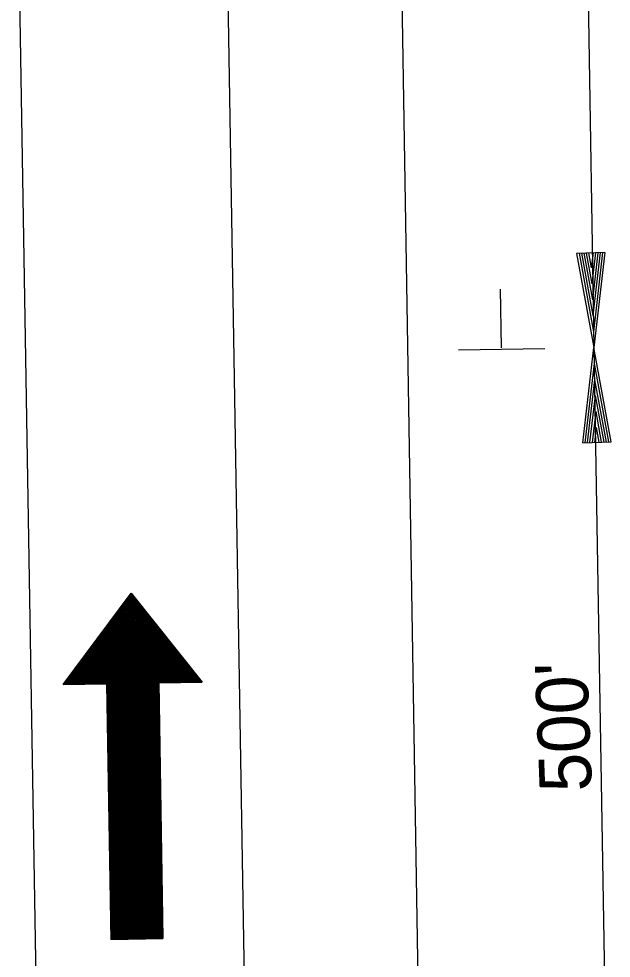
# Model space of a CAD drawing. Extents: x 1676063 to 1678026, y 228339 to 229904.
# Drawn here: x 1677124.4 to 1677192.4, y 228807.7 to 228915.5 of the extents above; entities that cross this region are included whole.
import ezdxf

# ---------------------------------------------------------------- set-up
doc = ezdxf.new("R2010")
doc.units = 0
for name, color, linetype in [('R_Annotation', 7, 'Continuous'), ('R_Draft', 7, 'Continuous'), ('R_MOT', 7, 'Continuous')]:
    doc.layers.add(name, color=color, linetype=linetype)

msp = doc.modelspace()

# ---------------------------------------------------------------- linework, layer by layer
at = {"layer": 'R_Draft'}
for p, q in [((1677188.75, 228977.78), (1677190.41, 228877.79)), ((1677175.46, 228491.33), (1677168.26, 228925.28)), ((1677131.58, 228490.6), (1677124.38, 228924.55)), ((1677155.51, 228491), (1677148.32, 228924.95)), ((1677191.68, 228888.72), (1677188.42, 228888.61)), ((1677188.42, 228888.61), (1677190.41, 228877.79)), ((1677188.7, 228888.62), (1677190.35, 228879.61)), ((1677188.97, 228888.63), (1677190.29, 228881.47)), ((1677189.24, 228888.64), (1677190.23, 228883.29)), ((1677189.52, 228888.65), (1677190.17, 228885.13)), ((1677189.8, 228888.66), (1677190.11, 228886.95)), ((1677190.31, 228888.67), (1677190.11, 228886.95)), ((1677190.58, 228888.68), (1677190.17, 228885.13)), ((1677190.86, 228888.69), (1677190.23, 228883.29)), ((1677191.13, 228888.7), (1677190.29, 228881.47)), ((1677191.41, 228888.71), (1677190.35, 228879.61)), ((1677191.68, 228888.72), (1677190.41, 228877.79)), ((1677179.8, 228877.76), (1677179.69, 228884.51)), ((1677174.87, 228877.53), (1677184.77, 228877.7)), ((1677189.13, 228866.86), (1677190.41, 228877.79)), ((1677190.41, 228877.79), (1677192.07, 228777.8)), ((1677192.4, 228866.97), (1677190.41, 228877.79)), ((1677189.41, 228866.87), (1677190.47, 228875.97)), ((1677192.12, 228866.96), (1677190.47, 228875.97)), ((1677189.68, 228866.88), (1677190.53, 228874.1)), ((1677191.84, 228866.95), (1677190.53, 228874.1)), ((1677189.95, 228866.89), (1677190.59, 228872.29)), ((1677191.58, 228866.94), (1677190.59, 228872.29)), ((1677190.23, 228866.9), (1677190.65, 228870.45)), ((1677191.3, 228866.93), (1677190.65, 228870.45)), ((1677190.51, 228866.91), (1677190.71, 228868.63)), ((1677191.02, 228866.92), (1677190.71, 228868.63)), ((1677189.13, 228866.86), (1677192.4, 228866.97)), ((1677129.48, 228839.11), (1677137.28, 228849.6)), ((1677137.28, 228849.6), (1677145.43, 228839.37)), ((1677129.48, 228839.11), (1677134.46, 228839.19)), ((1677134.46, 228839.19), (1677134.95, 228809.84)), ((1677140.45, 228839.29), (1677145.43, 228839.37)), ((1677140.45, 228839.29), (1677140.93, 228809.94)), ((1677134.95, 228809.84), (1677140.93, 228809.94))]:
    msp.add_line(p, q, dxfattribs=at)
at = {"layer": 'R_MOT'}
for p, q in [((1677137.55, 228849.27), (1677137.25, 228849.55)), ((1677143.84, 228841.37), (1677136.47, 228848.5)), ((1677143.36, 228841.97), (1677136.53, 228848.58)), ((1677142.87, 228842.58), (1677136.59, 228848.66)), ((1677142.39, 228843.19), (1677136.65, 228848.74)), ((1677141.9, 228843.8), (1677136.71, 228848.82)), ((1677141.42, 228844.4), (1677136.77, 228848.9)), ((1677140.94, 228845.01), (1677136.83, 228848.99)), ((1677140.45, 228845.62), (1677136.89, 228849.07)), ((1677139.97, 228846.23), (1677136.95, 228849.15)), ((1677139.48, 228846.83), (1677137.01, 228849.23)), ((1677139, 228847.44), (1677137.07, 228849.31)), ((1677138.51, 228848.05), (1677137.13, 228849.39)), ((1677138.03, 228848.66), (1677137.19, 228849.47)), ((1677144.06, 228839.35), (1677135.68, 228847.45)), ((1677144.2, 228839.35), (1677135.74, 228847.53)), ((1677144.34, 228839.35), (1677135.8, 228847.61)), ((1677144.48, 228839.35), (1677135.87, 228847.69)), ((1677144.62, 228839.36), (1677135.93, 228847.77)), ((1677144.77, 228839.36), (1677135.99, 228847.85)), ((1677144.91, 228839.36), (1677136.05, 228847.93)), ((1677145.05, 228839.36), (1677136.11, 228848.01)), ((1677145.19, 228839.37), (1677136.17, 228848.1)), ((1677145.33, 228839.37), (1677136.23, 228848.18)), ((1677145.29, 228839.54), (1677136.29, 228848.26)), ((1677144.81, 228840.15), (1677136.35, 228848.34)), ((1677144.33, 228840.76), (1677136.41, 228848.42)), ((1677142.08, 228839.31), (1677134.84, 228846.32)), ((1677142.22, 228839.32), (1677134.9, 228846.4)), ((1677142.36, 228839.32), (1677134.96, 228846.48)), ((1677142.5, 228839.32), (1677135.02, 228846.56)), ((1677142.65, 228839.32), (1677135.08, 228846.64)), ((1677142.79, 228839.33), (1677135.14, 228846.72)), ((1677142.93, 228839.33), (1677135.2, 228846.8)), ((1677143.07, 228839.33), (1677135.26, 228846.88)), ((1677143.21, 228839.33), (1677135.32, 228846.96)), ((1677143.35, 228839.34), (1677135.38, 228847.04)), ((1677143.49, 228839.34), (1677135.44, 228847.13)), ((1677143.63, 228839.34), (1677135.5, 228847.21)), ((1677143.78, 228839.34), (1677135.56, 228847.29)), ((1677143.92, 228839.34), (1677135.62, 228847.37)), ((1677140.45, 228839.08), (1677134.06, 228845.26)), ((1677140.45, 228839.22), (1677134.12, 228845.35)), ((1677140.52, 228839.29), (1677134.18, 228845.43)), ((1677140.67, 228839.29), (1677134.24, 228845.51)), ((1677140.81, 228839.29), (1677134.3, 228845.59)), ((1677140.95, 228839.3), (1677134.36, 228845.67)), ((1677141.09, 228839.3), (1677134.42, 228845.75)), ((1677141.23, 228839.3), (1677134.48, 228845.83)), ((1677141.37, 228839.3), (1677134.54, 228845.91)), ((1677141.51, 228839.3), (1677134.6, 228845.99)), ((1677141.66, 228839.31), (1677134.66, 228846.07)), ((1677141.8, 228839.31), (1677134.72, 228846.15)), ((1677141.94, 228839.31), (1677134.78, 228846.24)), ((1677140.48, 228837.24), (1677133.28, 228844.21)), ((1677140.48, 228837.39), (1677133.34, 228844.29)), ((1677140.48, 228837.53), (1677133.4, 228844.37)), ((1677140.47, 228837.67), (1677133.46, 228844.46)), ((1677140.47, 228837.81), (1677133.52, 228844.54)), ((1677140.47, 228837.95), (1677133.58, 228844.62)), ((1677140.47, 228838.09), (1677133.64, 228844.7)), ((1677140.46, 228838.23), (1677133.7, 228844.78)), ((1677140.46, 228838.38), (1677133.76, 228844.86)), ((1677140.46, 228838.52), (1677133.82, 228844.94)), ((1677140.46, 228838.66), (1677133.88, 228845.02)), ((1677140.45, 228838.8), (1677133.94, 228845.1)), ((1677140.45, 228838.94), (1677134, 228845.18)), ((1677140.51, 228835.26), (1677132.43, 228843.08)), ((1677140.51, 228835.41), (1677132.49, 228843.16)), ((1677140.51, 228835.55), (1677132.55, 228843.24)), ((1677140.51, 228835.69), (1677132.61, 228843.32)), ((1677140.5, 228835.83), (1677132.67, 228843.4)), ((1677140.5, 228835.97), (1677132.73, 228843.48)), ((1677140.5, 228836.11), (1677132.79, 228843.57)), ((1677140.5, 228836.25), (1677132.86, 228843.65)), ((1677140.49, 228836.4), (1677132.92, 228843.73)), ((1677140.49, 228836.54), (1677132.98, 228843.81)), ((1677140.49, 228836.68), (1677133.04, 228843.89)), ((1677140.49, 228836.82), (1677133.1, 228843.97)), ((1677140.48, 228836.96), (1677133.16, 228844.05)), ((1677140.48, 228837.1), (1677133.22, 228844.13)), ((1677140.54, 228833.43), (1677131.65, 228842.03)), ((1677140.54, 228833.57), (1677131.71, 228842.11)), ((1677140.54, 228833.71), (1677131.77, 228842.19)), ((1677140.54, 228833.85), (1677131.83, 228842.27)), ((1677140.53, 228833.99), (1677131.89, 228842.35)), ((1677140.53, 228834.13), (1677131.95, 228842.43)), ((1677140.53, 228834.27), (1677132.01, 228842.51)), ((1677140.53, 228834.42), (1677132.07, 228842.59)), ((1677140.52, 228834.56), (1677132.13, 228842.68)), ((1677140.52, 228834.7), (1677132.19, 228842.76)), ((1677140.52, 228834.84), (1677132.25, 228842.84)), ((1677140.52, 228834.98), (1677132.31, 228842.92)), ((1677140.52, 228835.12), (1677132.37, 228843)), ((1677132.75, 228839.16), (1677130.87, 228840.98)), ((1677132.89, 228839.16), (1677130.93, 228841.06)), ((1677133.03, 228839.16), (1677130.99, 228841.14)), ((1677133.17, 228839.17), (1677131.05, 228841.22)), ((1677133.31, 228839.17), (1677131.11, 228841.3)), ((1677133.45, 228839.17), (1677131.17, 228841.38)), ((1677133.6, 228839.17), (1677131.23, 228841.46)), ((1677133.74, 228839.18), (1677131.29, 228841.54)), ((1677133.88, 228839.18), (1677131.35, 228841.62)), ((1677134.02, 228839.18), (1677131.41, 228841.7)), ((1677134.16, 228839.18), (1677131.47, 228841.79)), ((1677134.3, 228839.19), (1677131.53, 228841.87)), ((1677134.44, 228839.19), (1677131.59, 228841.95)), ((1677130.77, 228839.13), (1677130.03, 228839.84)), ((1677130.91, 228839.13), (1677130.09, 228839.93)), ((1677131.05, 228839.13), (1677130.15, 228840.01)), ((1677131.19, 228839.13), (1677130.21, 228840.09)), ((1677131.33, 228839.14), (1677130.27, 228840.17)), ((1677131.47, 228839.14), (1677130.33, 228840.25)), ((1677131.62, 228839.14), (1677130.39, 228840.33)), ((1677131.76, 228839.14), (1677130.45, 228840.41)), ((1677131.9, 228839.15), (1677130.51, 228840.49)), ((1677132.04, 228839.15), (1677130.57, 228840.57)), ((1677132.18, 228839.15), (1677130.63, 228840.65)), ((1677132.32, 228839.15), (1677130.69, 228840.73)), ((1677132.46, 228839.15), (1677130.75, 228840.82)), ((1677132.61, 228839.16), (1677130.81, 228840.9)), ((1677129.49, 228839.11), (1677129.48, 228839.12)), ((1677129.64, 228839.11), (1677129.54, 228839.2)), ((1677129.78, 228839.11), (1677129.6, 228839.28)), ((1677129.92, 228839.11), (1677129.66, 228839.36)), ((1677130.06, 228839.12), (1677129.72, 228839.44)), ((1677130.2, 228839.12), (1677129.78, 228839.52)), ((1677130.34, 228839.12), (1677129.85, 228839.6)), ((1677130.48, 228839.12), (1677129.91, 228839.68)), ((1677130.63, 228839.12), (1677129.97, 228839.76)), ((1677140.55, 228833.28), (1677134.46, 228839.17)), ((1677140.55, 228833.14), (1677134.46, 228839.03)), ((1677140.55, 228833), (1677134.47, 228838.89)), ((1677140.55, 228832.86), (1677134.47, 228838.75)), ((1677140.56, 228832.72), (1677134.47, 228838.6)), ((1677140.56, 228832.58), (1677134.47, 228838.46)), ((1677140.56, 228832.44), (1677134.48, 228838.32)), ((1677140.56, 228832.3), (1677134.48, 228838.18)), ((1677140.56, 228832.15), (1677134.48, 228838.04)), ((1677140.57, 228832.01), (1677134.48, 228837.9)), ((1677140.57, 228831.87), (1677134.49, 228837.76)), ((1677140.57, 228831.73), (1677134.49, 228837.61)), ((1677140.57, 228831.59), (1677134.49, 228837.47)), ((1677140.58, 228831.45), (1677134.49, 228837.33)), ((1677140.58, 228831.31), (1677134.5, 228837.19)), ((1677140.58, 228831.16), (1677134.5, 228837.05)), ((1677140.58, 228831.02), (1677134.5, 228836.91)), ((1677140.59, 228830.88), (1677134.5, 228836.77)), ((1677140.59, 228830.74), (1677134.5, 228836.62)), ((1677140.59, 228830.6), (1677134.51, 228836.48)), ((1677140.59, 228830.46), (1677134.51, 228836.34)), ((1677140.59, 228830.32), (1677134.51, 228836.2)), ((1677140.6, 228830.17), (1677134.51, 228836.06)), ((1677140.6, 228830.03), (1677134.52, 228835.92)), ((1677140.6, 228829.89), (1677134.52, 228835.78)), ((1677140.6, 228829.75), (1677134.52, 228835.63)), ((1677140.61, 228829.61), (1677134.52, 228835.49)), ((1677140.61, 228829.47), (1677134.53, 228835.35)), ((1677140.61, 228829.33), (1677134.53, 228835.21)), ((1677140.61, 228829.18), (1677134.53, 228835.07)), ((1677140.62, 228829.04), (1677134.53, 228834.93)), ((1677140.62, 228828.9), (1677134.54, 228834.79)), ((1677140.62, 228828.76), (1677134.54, 228834.64)), ((1677140.62, 228828.62), (1677134.54, 228834.5)), ((1677140.63, 228828.48), (1677134.54, 228834.36)), ((1677140.63, 228828.34), (1677134.54, 228834.22)), ((1677140.63, 228828.19), (1677134.55, 228834.08)), ((1677140.63, 228828.05), (1677134.55, 228833.94)), ((1677140.63, 228827.91), (1677134.55, 228833.8)), ((1677140.64, 228827.77), (1677134.55, 228833.65)), ((1677140.64, 228827.63), (1677134.56, 228833.51)), ((1677140.64, 228827.49), (1677134.56, 228833.37)), ((1677140.64, 228827.35), (1677134.56, 228833.23)), ((1677140.65, 228827.2), (1677134.56, 228833.09)), ((1677140.65, 228827.06), (1677134.57, 228832.95)), ((1677140.65, 228826.92), (1677134.57, 228832.81)), ((1677140.65, 228826.78), (1677134.57, 228832.67)), ((1677140.66, 228826.64), (1677134.57, 228832.52)), ((1677140.66, 228826.5), (1677134.58, 228832.38)), ((1677140.66, 228826.36), (1677134.58, 228832.24)), ((1677140.66, 228826.21), (1677134.58, 228832.1)), ((1677140.67, 228826.07), (1677134.58, 228831.96)), ((1677140.67, 228825.93), (1677134.58, 228831.82)), ((1677140.67, 228825.79), (1677134.59, 228831.68)), ((1677140.67, 228825.65), (1677134.59, 228831.53)), ((1677140.67, 228825.51), (1677134.59, 228831.39)), ((1677140.68, 228825.37), (1677134.59, 228831.25)), ((1677140.68, 228825.23), (1677134.6, 228831.11)), ((1677140.68, 228825.08), (1677134.6, 228830.97)), ((1677140.68, 228824.94), (1677134.6, 228830.83)), ((1677140.69, 228824.8), (1677134.6, 228830.69)), ((1677140.69, 228824.66), (1677134.61, 228830.54)), ((1677140.69, 228824.52), (1677134.61, 228830.4)), ((1677140.69, 228824.38), (1677134.61, 228830.26)), ((1677140.7, 228824.24), (1677134.61, 228830.12)), ((1677140.7, 228824.09), (1677134.62, 228829.98)), ((1677140.7, 228823.95), (1677134.62, 228829.84)), ((1677140.7, 228823.81), (1677134.62, 228829.7)), ((1677140.71, 228823.67), (1677134.62, 228829.55)), ((1677140.71, 228823.53), (1677134.62, 228829.41)), ((1677140.71, 228823.39), (1677134.63, 228829.27)), ((1677140.71, 228823.25), (1677134.63, 228829.13)), ((1677140.71, 228823.1), (1677134.63, 228828.99)), ((1677140.72, 228822.96), (1677134.63, 228828.85)), ((1677140.72, 228822.82), (1677134.64, 228828.71)), ((1677140.72, 228822.68), (1677134.64, 228828.56)), ((1677140.72, 228822.54), (1677134.64, 228828.42)), ((1677140.73, 228822.4), (1677134.64, 228828.28)), ((1677140.73, 228822.26), (1677134.65, 228828.14)), ((1677140.73, 228822.11), (1677134.65, 228828)), ((1677140.73, 228821.97), (1677134.65, 228827.86)), ((1677140.74, 228821.83), (1677134.65, 228827.72)), ((1677140.74, 228821.69), (1677134.65, 228827.57)), ((1677140.74, 228821.55), (1677134.66, 228827.43)), ((1677140.74, 228821.41), (1677134.66, 228827.29)), ((1677140.74, 228821.27), (1677134.66, 228827.15)), ((1677140.75, 228821.12), (1677134.66, 228827.01)), ((1677140.75, 228820.98), (1677134.67, 228826.87)), ((1677140.75, 228820.84), (1677134.67, 228826.73)), ((1677140.75, 228820.7), (1677134.67, 228826.58)), ((1677140.76, 228820.56), (1677134.67, 228826.44)), ((1677140.76, 228820.42), (1677134.68, 228826.3)), ((1677140.76, 228820.28), (1677134.68, 228826.16)), ((1677140.76, 228820.13), (1677134.68, 228826.02)), ((1677140.77, 228819.99), (1677134.68, 228825.88)), ((1677140.77, 228819.85), (1677134.69, 228825.74)), ((1677140.77, 228819.71), (1677134.69, 228825.59)), ((1677140.77, 228819.57), (1677134.69, 228825.45)), ((1677140.78, 228819.43), (1677134.69, 228825.31)), ((1677140.78, 228819.29), (1677134.69, 228825.17)), ((1677140.78, 228819.14), (1677134.7, 228825.03)), ((1677140.78, 228819), (1677134.7, 228824.89)), ((1677140.78, 228818.86), (1677134.7, 228824.75)), ((1677140.79, 228818.72), (1677134.7, 228824.61)), ((1677140.79, 228818.58), (1677134.71, 228824.46)), ((1677140.79, 228818.44), (1677134.71, 228824.32)), ((1677140.79, 228818.3), (1677134.71, 228824.18)), ((1677140.8, 228818.15), (1677134.71, 228824.04)), ((1677140.8, 228818.01), (1677134.72, 228823.9)), ((1677140.8, 228817.87), (1677134.72, 228823.76)), ((1677140.8, 228817.73), (1677134.72, 228823.62)), ((1677140.81, 228817.59), (1677134.72, 228823.47)), ((1677140.81, 228817.45), (1677134.73, 228823.33)), ((1677140.81, 228817.31), (1677134.73, 228823.19)), ((1677140.81, 228817.17), (1677134.73, 228823.05)), ((1677140.82, 228817.02), (1677134.73, 228822.91)), ((1677140.82, 228816.88), (1677134.73, 228822.77)), ((1677140.82, 228816.74), (1677134.74, 228822.63)), ((1677140.82, 228816.6), (1677134.74, 228822.48)), ((1677140.82, 228816.46), (1677134.74, 228822.34)), ((1677140.83, 228816.32), (1677134.74, 228822.2)), ((1677140.83, 228816.18), (1677134.75, 228822.06)), ((1677140.83, 228816.03), (1677134.75, 228821.92)), ((1677140.83, 228815.89), (1677134.75, 228821.78)), ((1677140.84, 228815.75), (1677134.75, 228821.64)), ((1677140.84, 228815.61), (1677134.76, 228821.49)), ((1677140.84, 228815.47), (1677134.76, 228821.35)), ((1677140.84, 228815.33), (1677134.76, 228821.21)), ((1677140.85, 228815.19), (1677134.76, 228821.07)), ((1677140.85, 228815.04), (1677134.77, 228820.93)), ((1677140.85, 228814.9), (1677134.77, 228820.79)), ((1677140.85, 228814.76), (1677134.77, 228820.65)), ((1677140.86, 228814.62), (1677134.77, 228820.5)), ((1677140.86, 228814.48), (1677134.77, 228820.36)), ((1677140.86, 228814.34), (1677134.78, 228820.22)), ((1677140.86, 228814.2), (1677134.78, 228820.08)), ((1677140.86, 228814.05), (1677134.78, 228819.94)), ((1677140.87, 228813.91), (1677134.78, 228819.8)), ((1677140.87, 228813.77), (1677134.79, 228819.66)), ((1677140.87, 228813.63), (1677134.79, 228819.51)), ((1677140.87, 228813.49), (1677134.79, 228819.37)), ((1677140.88, 228813.35), (1677134.79, 228819.23)), ((1677140.88, 228813.21), (1677134.8, 228819.09)), ((1677140.88, 228813.06), (1677134.8, 228818.95)), ((1677140.88, 228812.92), (1677134.8, 228818.81)), ((1677140.89, 228812.78), (1677134.8, 228818.67)), ((1677140.89, 228812.64), (1677134.8, 228818.52)), ((1677140.89, 228812.5), (1677134.81, 228818.38)), ((1677140.89, 228812.36), (1677134.81, 228818.24)), ((1677140.89, 228812.22), (1677134.81, 228818.1)), ((1677140.9, 228812.07), (1677134.81, 228817.96)), ((1677140.9, 228811.93), (1677134.82, 228817.82)), ((1677140.9, 228811.79), (1677134.82, 228817.68)), ((1677140.9, 228811.65), (1677134.82, 228817.54)), ((1677140.91, 228811.51), (1677134.82, 228817.39)), ((1677140.91, 228811.37), (1677134.83, 228817.25)), ((1677140.91, 228811.23), (1677134.83, 228817.11)), ((1677140.91, 228811.08), (1677134.83, 228816.97)), ((1677140.92, 228810.94), (1677134.83, 228816.83)), ((1677140.92, 228810.8), (1677134.84, 228816.69)), ((1677140.92, 228810.66), (1677134.84, 228816.55)), ((1677140.92, 228810.52), (1677134.84, 228816.4)), ((1677140.93, 228810.38), (1677134.84, 228816.26)), ((1677140.93, 228810.24), (1677134.84, 228816.12)), ((1677140.93, 228810.1), (1677134.85, 228815.98)), ((1677140.93, 228809.95), (1677134.85, 228815.84)), ((1677140.8, 228809.94), (1677134.85, 228815.7)), ((1677140.66, 228809.94), (1677134.85, 228815.56)), ((1677140.52, 228809.94), (1677134.86, 228815.41)), ((1677140.38, 228809.93), (1677134.86, 228815.27)), ((1677140.24, 228809.93), (1677134.86, 228815.13)), ((1677140.09, 228809.93), (1677134.86, 228814.99)), ((1677139.95, 228809.93), (1677134.87, 228814.85)), ((1677139.81, 228809.93), (1677134.87, 228814.71)), ((1677139.67, 228809.92), (1677134.87, 228814.57)), ((1677139.53, 228809.92), (1677134.87, 228814.42)), ((1677139.39, 228809.92), (1677134.88, 228814.28)), ((1677139.25, 228809.92), (1677134.88, 228814.14)), ((1677139.1, 228809.91), (1677134.88, 228814)), ((1677138.96, 228809.91), (1677134.88, 228813.86)), ((1677138.82, 228809.91), (1677134.88, 228813.72)), ((1677138.68, 228809.91), (1677134.89, 228813.58)), ((1677138.54, 228809.9), (1677134.89, 228813.43)), ((1677138.4, 228809.9), (1677134.89, 228813.29)), ((1677138.26, 228809.9), (1677134.89, 228813.15)), ((1677138.11, 228809.9), (1677134.9, 228813.01)), ((1677137.97, 228809.89), (1677134.9, 228812.87)), ((1677137.83, 228809.89), (1677134.9, 228812.73)), ((1677137.69, 228809.89), (1677134.9, 228812.59)), ((1677137.55, 228809.89), (1677134.91, 228812.44)), ((1677137.41, 228809.89), (1677134.91, 228812.3)), ((1677137.27, 228809.88), (1677134.91, 228812.16)), ((1677137.12, 228809.88), (1677134.91, 228812.02)), ((1677136.98, 228809.88), (1677134.92, 228811.88)), ((1677136.84, 228809.88), (1677134.92, 228811.74)), ((1677136.7, 228809.87), (1677134.92, 228811.6)), ((1677136.56, 228809.87), (1677134.92, 228811.45)), ((1677136.42, 228809.87), (1677134.92, 228811.31)), ((1677136.28, 228809.87), (1677134.93, 228811.17)), ((1677136.13, 228809.86), (1677134.93, 228811.03)), ((1677135.99, 228809.86), (1677134.93, 228810.89)), ((1677135.85, 228809.86), (1677134.93, 228810.75)), ((1677135.71, 228809.86), (1677134.94, 228810.61)), ((1677135.57, 228809.86), (1677134.94, 228810.46)), ((1677135.43, 228809.85), (1677134.94, 228810.32)), ((1677135.29, 228809.85), (1677134.94, 228810.18)), ((1677135.14, 228809.85), (1677134.95, 228810.04)), ((1677135, 228809.85), (1677134.95, 228809.9))]:
    msp.add_line(p, q, dxfattribs=at)

# ---------------------------------------------------------------- texts
at = {"layer": 'R_Annotation'}
msp.add_text("500'", height=6, rotation=92.1801, dxfattribs=at).set_placement((1677190.19, 228826.89))

doc.saveas('drawing.dxf')
